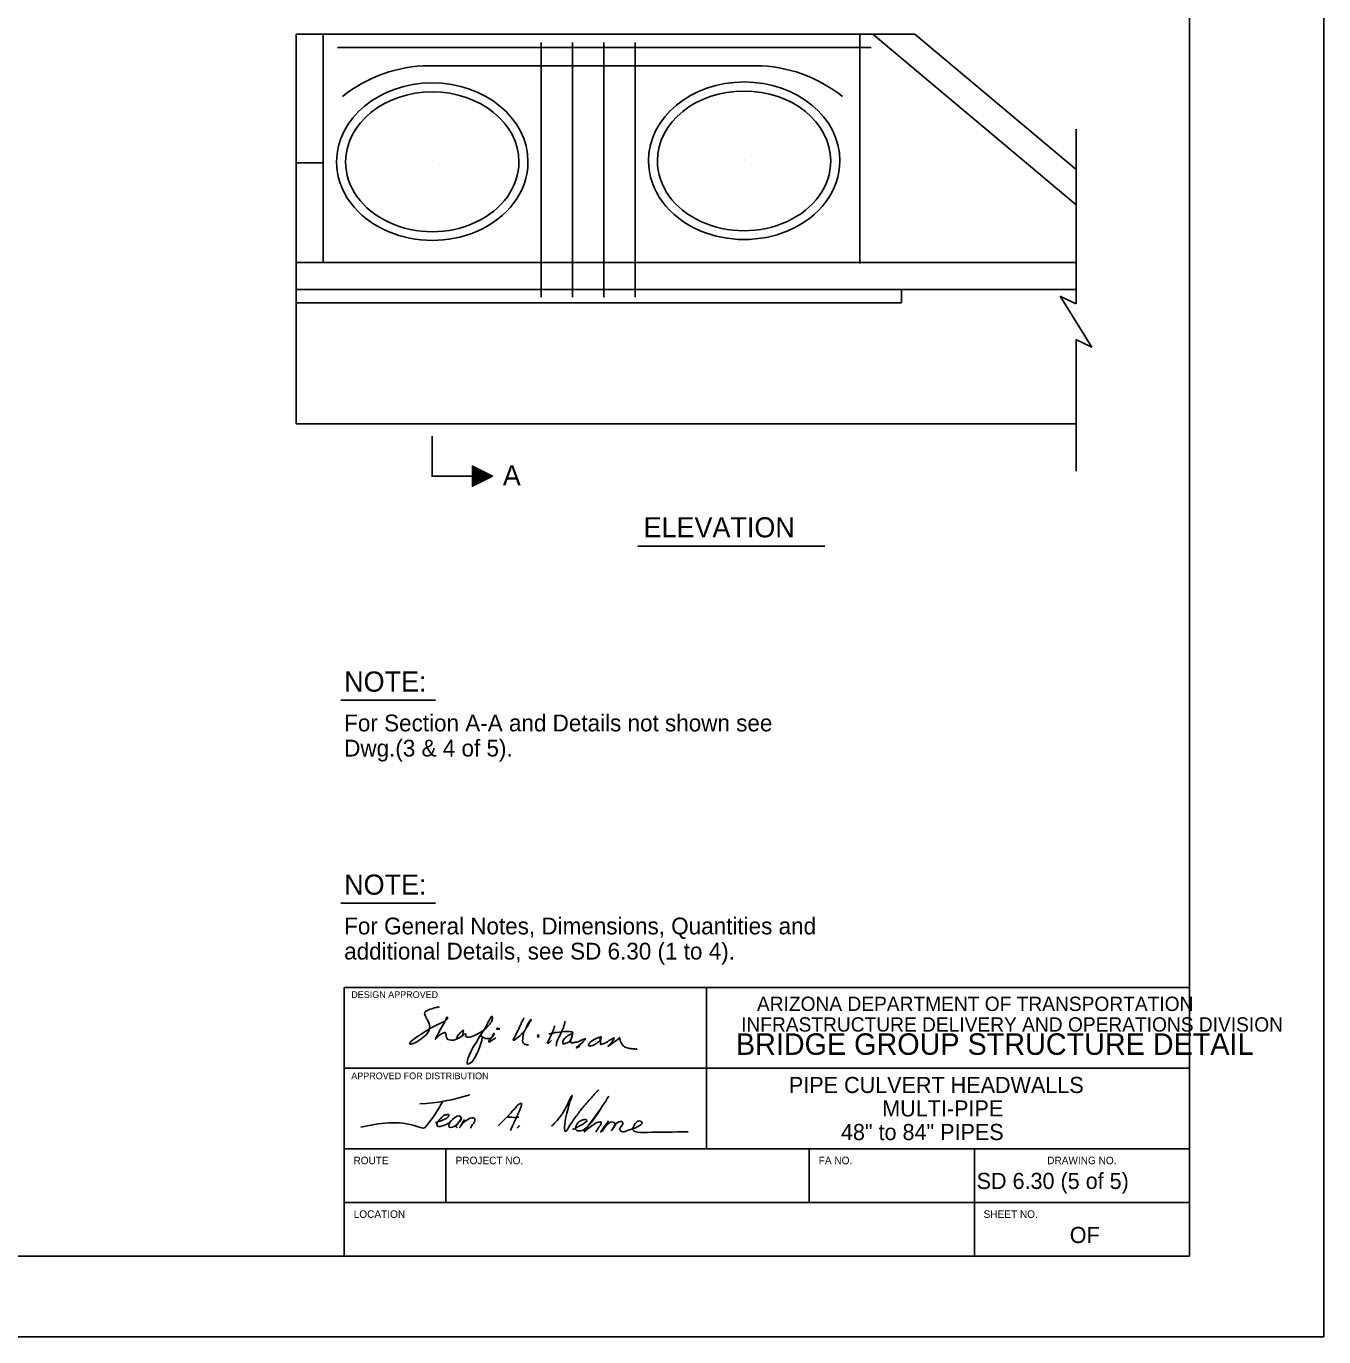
# Model space of a CAD drawing. Extents: x -0.08 to 2.83, y -0.03 to 1.92.
# Drawn here: x 1.827 to 2.833, y 0 to 1.016 of the extents above; entities that cross this region are included whole.
import ezdxf

# ---------------------------------------------------------------- set-up
doc = ezdxf.new("R2010")
doc.units = 0
for name, color, linetype in [('50', 7, 'Continuous'), ('51', 7, 'Continuous'), ('52', 7, 'Continuous'), ('55', 7, 'Continuous'), ('57', 7, 'Continuous'), ('62', 7, 'Continuous'), ('63', 7, 'Continuous')]:
    doc.layers.add(name, color=color, linetype=linetype)

msp = doc.modelspace()

# ---------------------------------------------------------------- linework, layer by layer
at = {"layer": '50'}
for p, q in [((2.0367, 1.0099), (2.5163, 1.0099)), ((2.0367, 0.8951), (2.0367, 1.0099)), ((2.0576, 0.8328), (2.0576, 1.0099)), ((2.4737, 0.8321), (2.4737, 1.0099)), ((2.4838, 1.0099), (2.6414, 0.8777)), ((2.5163, 1.0099), (2.6413, 0.905)), ((2.0367, 0.7078), (2.0367, 0.9944)), ((2.6414, 0.9363), (2.6414, 0.8008)), ((2.0576, 0.9102), (2.0367, 0.9102)), ((2.0749, 0.911), (2.0749, 0.911)), ((2.1424, 0.9117), (2.1424, 0.9117)), ((2.3167, 0.9117), (2.3167, 0.9117)), ((2.384, 0.9117), (2.384, 0.9117)), ((2.3842, 0.9124), (2.3842, 0.9124)), ((2.0367, 0.8328), (2.6414, 0.8328)), ((2.0367, 0.812), (2.6414, 0.812)), ((2.5059, 0.8016), (2.5059, 0.812)), ((2.6289, 0.8069), (2.6412, 0.8008)), ((2.6289, 0.8069), (2.6535, 0.7672)), ((2.0367, 0.8016), (2.5059, 0.8016)), ((2.6412, 0.787), (2.6412, 0.787)), ((2.6412, 0.7733), (2.6535, 0.7672)), ((2.6414, 0.7733), (2.6414, 0.6712)), ((2.0367, 0.7078), (2.6414, 0.7078))]:
    msp.add_line(p, q, dxfattribs=at)
at = {"layer": '51'}
for p, q in [((2.0687, 0.9995), (2.4825, 0.9995)), ((2.2266, 0.806), (2.2266, 1.0036)), ((2.2509, 0.806), (2.2509, 1.0036)), ((2.2752, 0.806), (2.2752, 1.0036)), ((2.2995, 0.806), (2.2995, 1.0036)), ((2.1396, 0.9855), (2.393, 0.9855))]:
    msp.add_line(p, q, dxfattribs=at)
for centre, start, end in [((2.1406, 0.8765), 90.5076, 128.604), ((2.3921, 0.8765), 51.396, 89.4924)]:
    msp.add_arc(centre, 0.109, start, end, dxfattribs=at)
at = {"layer": '52'}
for centre, major_axis, ratio, start_param, end_param in [((2.1422, 0.911), (-0.0742, 0), 0.824448, 3.141593, 6.283185), ((2.384, 0.9117), (-0.0742, 0), 0.824448, 3.141593, 6.283185), ((2.3839, 0.9117), (-0.0672, 0), 0.80633, 3.141593, 6.283185), ((2.1422, 0.911), (-0.0672, 0), 0.80633, 3.141593, 6.283185), ((2.1422, 0.911), (-0.0742, 0), 0.821526, 0, 1.092867), ((2.1422, 0.911), (-0.0672, 0), 0.80633, 0, 3.141593), ((2.1422, 0.911), (-0.0742, 0), 0.821526, 2.043996, 3.141597), ((2.384, 0.9117), (-0.0742, 0), 0.821526, 0, 1.092867), ((2.3839, 0.9117), (-0.0672, 0), 0.80633, 0, 3.141593), ((2.384, 0.9117), (-0.0742, 0), 0.821526, 2.043996, 3.141597), ((2.1422, 0.911), (-0.0742, 0), 0.821526, 1.092853, 2.043994), ((2.384, 0.9117), (-0.0742, 0), 0.821526, 1.092853, 2.043994)]:
    msp.add_ellipse(centre, major_axis=major_axis, ratio=ratio, start_param=start_param, end_param=end_param, dxfattribs=at)
at = {"layer": '55'}
msp.add_lwpolyline([(2.142, 0.6984), (2.142, 0.6672), (2.1733, 0.6672), (2.1733, 0.6594), (2.1889, 0.6673), (2.1733, 0.6751), (2.1733, 0.6673), (2.1744, 0.6672), (2.1744, 0.661), (2.1869, 0.6673), (2.1744, 0.6735), (2.1744, 0.6673), (2.1754, 0.6672), (2.1754, 0.6623), (2.1854, 0.6673), (2.1754, 0.6723), (2.1754, 0.6673), (2.1763, 0.6672), (2.1763, 0.6637), (2.1833, 0.6672), (2.1763, 0.6708), (2.1763, 0.6673), (2.1773, 0.6672), (2.1773, 0.6647), (2.1822, 0.6672), (2.1773, 0.6697), (2.1773, 0.6673), (2.1778, 0.6672), (2.1778, 0.6658), (2.1807, 0.6672), (2.1778, 0.6687), (2.1778, 0.6673), (2.1784, 0.6672), (2.1784, 0.6666), (2.1795, 0.6672), (2.1784, 0.6677), (2.1784, 0.6673)], dxfattribs=at)
at = {"layer": '57'}
for p, q in [((2.3015, 0.613), (2.4465, 0.613)), ((2.0713, 0.4935), (2.1448, 0.4935)), ((2.0713, 0.3361), (2.1448, 0.3361))]:
    msp.add_line(p, q, dxfattribs=at)
for points in [[(2.1477, 0.2556), (2.1468, 0.2557), (2.1458, 0.2554), (2.1449, 0.2553), (2.144, 0.255), (2.1431, 0.2548), (2.142, 0.2543), (2.1404, 0.2539), (2.139, 0.2533), (2.1381, 0.2528), (2.1376, 0.2526), (2.1371, 0.2524), (2.1366, 0.2519), (2.1364, 0.2514), (2.1363, 0.2504), (2.1365, 0.2499), (2.1367, 0.2491), (2.1371, 0.2482), (2.1375, 0.2473), (2.138, 0.2463), (2.1385, 0.2457), (2.1391, 0.2444), (2.1395, 0.2436), (2.1399, 0.2429), (2.1401, 0.2414), (2.1402, 0.2405), (2.1401, 0.2395), (2.1397, 0.238), (2.1389, 0.2363), (2.1382, 0.2352), (2.1366, 0.2333), (2.1351, 0.2323), (2.1333, 0.2307), (2.1317, 0.2297), (2.1303, 0.2288), (2.1288, 0.228), (2.1273, 0.2273), (2.1258, 0.2268), (2.125, 0.2269), (2.1246, 0.2276), (2.1248, 0.228), (2.1254, 0.2285), (2.1258, 0.2291), (2.1269, 0.23), (2.129, 0.2315), (2.1299, 0.2322), (2.1315, 0.2334), (2.1333, 0.2345), (2.1352, 0.2357), (2.1368, 0.2366), (2.1413, 0.2395), (2.1456, 0.2416), (2.1476, 0.2427), (2.1498, 0.2437), (2.1514, 0.2445), (2.1527, 0.2452), (2.1536, 0.2459), (2.154, 0.2465), (2.154, 0.2477), (2.1536, 0.2479), (2.1534, 0.2477), (2.1533, 0.2474), (2.1519, 0.2441), (2.151, 0.2423), (2.1479, 0.2371), (2.1462, 0.2339), (2.1454, 0.2326), (2.1446, 0.2309), (2.1447, 0.2307), (2.1462, 0.2324), (2.1479, 0.2338), (2.1493, 0.2349), (2.1504, 0.2355), (2.1503, 0.2355), (2.1517, 0.236), (2.1523, 0.2358), (2.1525, 0.2355), (2.1529, 0.2341), (2.153, 0.2328), (2.1535, 0.2316), (2.1542, 0.2306), (2.1566, 0.2301), (2.159, 0.2301), (2.1606, 0.2308), (2.1633, 0.2318), (2.1649, 0.233), (2.1659, 0.2341), (2.1662, 0.2362), (2.1665, 0.2374), (2.1662, 0.2377), (2.1657, 0.2374), (2.1644, 0.2361), (2.163, 0.2346), (2.1624, 0.234), (2.1617, 0.2332), (2.1613, 0.2319), (2.1615, 0.2311), (2.1631, 0.2319), (2.165, 0.2331), (2.1666, 0.2342), (2.1675, 0.2349)], [(2.1675, 0.2349), (2.1677, 0.235), (2.168, 0.235), (2.1683, 0.2343), (2.1681, 0.2332), (2.1685, 0.2325), (2.1694, 0.2323), (2.1707, 0.2323), (2.1722, 0.2326), (2.1743, 0.2334), (2.1771, 0.2347), (2.1792, 0.2359), (2.1811, 0.237), (2.184, 0.2394), (2.1867, 0.2425), (2.1874, 0.2434), (2.188, 0.2441), (2.1888, 0.2468), (2.1886, 0.2482), (2.188, 0.2484), (2.1852, 0.2437), (2.1836, 0.2401), (2.1786, 0.2322), (2.1764, 0.2285), (2.1737, 0.2244), (2.1708, 0.2182), (2.1698, 0.2158), (2.1692, 0.2126), (2.1693, 0.2119), (2.1701, 0.2114), (2.1719, 0.2123), (2.173, 0.2133), (2.1749, 0.2161), (2.1775, 0.2209), (2.1789, 0.2242), (2.1797, 0.2265), (2.1806, 0.2298), (2.1808, 0.2318), (2.1807, 0.2332), (2.1801, 0.2336), (2.1797, 0.2338), (2.18, 0.2331), (2.1807, 0.2327), (2.1813, 0.2322), (2.1824, 0.2317), (2.1835, 0.2313), (2.1841, 0.2313), (2.1858, 0.2312), (2.1865, 0.2313), (2.1879, 0.2317), (2.1891, 0.2327), (2.1894, 0.233), (2.1901, 0.2346), (2.1902, 0.2351), (2.1898, 0.2354), (2.1884, 0.2324), (2.1867, 0.2305), (2.1863, 0.2297), (2.186, 0.229), (2.1862, 0.2285), (2.1886, 0.23), (2.1895, 0.2305), (2.1906, 0.2312), (2.1914, 0.2318)], [(2.2132, 0.2473), (2.2128, 0.2463), (2.2119, 0.2446), (2.2111, 0.2429), (2.2099, 0.24), (2.2092, 0.2388), (2.2084, 0.2371), (2.2075, 0.2353), (2.2066, 0.2336), (2.2059, 0.2321), (2.2052, 0.2309), (2.205, 0.2303), (2.205, 0.23), (2.2051, 0.2299), (2.2054, 0.2298), (2.2057, 0.23), (2.2065, 0.2305), (2.2074, 0.2312), (2.2088, 0.2323), (2.2101, 0.2334), (2.2113, 0.2347), (2.2122, 0.2357), (2.2133, 0.2367), (2.214, 0.2375), (2.2148, 0.239), (2.216, 0.2409), (2.2167, 0.242), (2.2178, 0.2441), (2.2184, 0.2448), (2.2189, 0.2456), (2.2189, 0.2458), (2.2188, 0.2459), (2.2187, 0.246), (2.2185, 0.2459), (2.2181, 0.2452), (2.2172, 0.2441), (2.216, 0.242), (2.2157, 0.2413), (2.2153, 0.2404), (2.2149, 0.2396), (2.2139, 0.2375), (2.2133, 0.236), (2.213, 0.2348), (2.2127, 0.2337), (2.2125, 0.2324), (2.2123, 0.2307), (2.2122, 0.2295), (2.2123, 0.2283), (2.2126, 0.2278), (2.2132, 0.2273), (2.2138, 0.2269), (2.2143, 0.2267), (2.215, 0.2265), (2.2156, 0.2264), (2.2162, 0.2264), (2.2167, 0.2264)], [(2.2447, 0.2448), (2.245, 0.2443), (2.245, 0.2437), (2.2449, 0.2432), (2.2447, 0.2423), (2.2443, 0.2408), (2.2439, 0.2397), (2.2432, 0.238), (2.2427, 0.237), (2.2421, 0.2359), (2.241, 0.2334), (2.2406, 0.2326), (2.2395, 0.2304), (2.2393, 0.23), (2.239, 0.2291), (2.2386, 0.2277), (2.2384, 0.2267), (2.2382, 0.2256), (2.2381, 0.2252)], [(2.1947, 0.2388), (2.1943, 0.2388), (2.1938, 0.2389), (2.1934, 0.2391), (2.1931, 0.2393), (2.1928, 0.2393), (2.1925, 0.2393), (2.1924, 0.2392), (2.1922, 0.239), (2.1922, 0.2389), (2.1922, 0.2386), (2.1925, 0.2385), (2.1927, 0.2385), (2.193, 0.2385), (2.1935, 0.2386), (2.1938, 0.2386), (2.1942, 0.2386), (2.1946, 0.2387), (2.1947, 0.2387)], [(2.2244, 0.2324), (2.2247, 0.2331), (2.2246, 0.2338), (2.2244, 0.2341), (2.2241, 0.2341), (2.224, 0.2339), (2.2239, 0.2332), (2.224, 0.2326), (2.2242, 0.2323), (2.2243, 0.2322), (2.2244, 0.2322), (2.2244, 0.2324)], [(2.2371, 0.2412), (2.2367, 0.24), (2.2364, 0.239), (2.2358, 0.2372), (2.235, 0.2353), (2.2346, 0.2345), (2.2341, 0.2333), (2.2333, 0.2317), (2.2327, 0.2306), (2.2322, 0.2297), (2.2317, 0.2288), (2.2315, 0.2282), (2.2315, 0.2278), (2.2316, 0.2276), (2.2318, 0.2276), (2.232, 0.2276), (2.2326, 0.228), (2.2331, 0.2284), (2.2334, 0.2286), (2.2336, 0.2288), (2.2338, 0.2289), (2.234, 0.2291), (2.2342, 0.2293), (2.2344, 0.2295), (2.2345, 0.2296), (2.2347, 0.2298)], [(2.2325, 0.2346), (2.2332, 0.2348), (2.2342, 0.235), (2.2357, 0.2354), (2.2374, 0.2358), (2.2388, 0.2359), (2.2409, 0.2362), (2.243, 0.2364), (2.2448, 0.2366), (2.2463, 0.2366), (2.2475, 0.2366), (2.2482, 0.2366), (2.2495, 0.2365), (2.2505, 0.2364), (2.2509, 0.2362), (2.2511, 0.2357), (2.2507, 0.2337), (2.2506, 0.2334), (2.2501, 0.2318), (2.2497, 0.2308), (2.2492, 0.2298), (2.249, 0.2294), (2.2488, 0.2291), (2.2486, 0.2288), (2.2479, 0.2285), (2.2467, 0.2278), (2.2457, 0.2276), (2.2449, 0.2273), (2.2445, 0.2272), (2.244, 0.2272), (2.2435, 0.2274), (2.2433, 0.2275), (2.2433, 0.2277), (2.2433, 0.2281), (2.2433, 0.2288), (2.2435, 0.2293), (2.2437, 0.2298), (2.2441, 0.2306), (2.2447, 0.2312), (2.2456, 0.2321), (2.2463, 0.2326), (2.2468, 0.233), (2.2474, 0.2335), (2.2481, 0.2339), (2.249, 0.2344), (2.2496, 0.2347), (2.2503, 0.235), (2.2505, 0.235), (2.2508, 0.2349), (2.2508, 0.2347), (2.2506, 0.2334), (2.2505, 0.2332), (2.2503, 0.2322), (2.2499, 0.231), (2.2495, 0.23), (2.2494, 0.2295), (2.2494, 0.2293), (2.2493, 0.2291), (2.2493, 0.2287), (2.2494, 0.2284), (2.2498, 0.2281), (2.2499, 0.228), (2.2501, 0.228), (2.2505, 0.228), (2.2511, 0.228), (2.2515, 0.228), (2.2519, 0.2281), (2.2525, 0.2282), (2.2531, 0.2283), (2.2537, 0.2284), (2.2544, 0.2285), (2.2551, 0.2288), (2.2563, 0.2293), (2.2578, 0.2299), (2.2589, 0.2304), (2.2597, 0.2307), (2.2602, 0.231), (2.2608, 0.2311), (2.2609, 0.231), (2.2606, 0.2304), (2.26, 0.2298), (2.2593, 0.229), (2.2589, 0.2286), (2.2583, 0.228), (2.2572, 0.227), (2.2541, 0.2242), (2.2538, 0.224), (2.2541, 0.2241), (2.255, 0.2245), (2.2558, 0.2249), (2.2563, 0.2251), (2.2566, 0.2253)], [(2.2723, 0.2303), (2.2721, 0.2318), (2.2715, 0.2323), (2.271, 0.2321), (2.2692, 0.2314), (2.2681, 0.2308), (2.2672, 0.2302), (2.2664, 0.2297), (2.2655, 0.229), (2.2647, 0.2284), (2.2642, 0.2278), (2.2637, 0.2272), (2.2634, 0.2266), (2.2634, 0.2263), (2.2634, 0.2259), (2.2637, 0.2256), (2.264, 0.2255), (2.2644, 0.2254), (2.2646, 0.2254), (2.2652, 0.2255), (2.2655, 0.2256), (2.2664, 0.2258), (2.2678, 0.2263), (2.2686, 0.2269), (2.2695, 0.2275), (2.2703, 0.2281), (2.2711, 0.2287), (2.2718, 0.2294), (2.2724, 0.2301), (2.2731, 0.2315), (2.2732, 0.2322), (2.273, 0.2327), (2.2727, 0.2323), (2.2726, 0.2317), (2.2726, 0.231), (2.2726, 0.2299), (2.2726, 0.2291), (2.2726, 0.2283), (2.2726, 0.2277), (2.2726, 0.2269), (2.2727, 0.2267), (2.2728, 0.2267), (2.2737, 0.227), (2.2747, 0.2272), (2.2754, 0.2275), (2.2761, 0.2279), (2.2764, 0.228), (2.2772, 0.2284), (2.278, 0.2288), (2.2792, 0.2296), (2.2804, 0.2302), (2.2817, 0.2309), (2.2821, 0.2312), (2.283, 0.2318), (2.2831, 0.2317), (2.2829, 0.231), (2.2826, 0.2303), (2.2822, 0.2296), (2.2816, 0.2287), (2.2811, 0.2281), (2.2799, 0.2268), (2.2786, 0.2256), (2.2785, 0.2253), (2.2787, 0.2253), (2.2801, 0.2263), (2.2819, 0.2276), (2.2834, 0.2286), (2.2845, 0.2294), (2.2857, 0.2303), (2.287, 0.2318), (2.2871, 0.2318), (2.2873, 0.2321), (2.2874, 0.232), (2.2877, 0.2307), (2.2879, 0.2299), (2.2882, 0.229), (2.2885, 0.2284), (2.2888, 0.2277), (2.2891, 0.2271), (2.2896, 0.2263), (2.29, 0.2258), (2.2905, 0.2255), (2.2909, 0.2251), (2.2913, 0.2249), (2.2923, 0.2244), (2.2932, 0.2241), (2.2944, 0.2237), (2.2951, 0.2236), (2.2961, 0.2234), (2.297, 0.2233), (2.298, 0.2232), (2.2988, 0.2232), (2.2995, 0.2231), (2.3005, 0.223), (2.3009, 0.2229), (2.3007, 0.2231), (2.3004, 0.2233), (2.3001, 0.2235), (2.2999, 0.2236)]]:
    msp.add_lwpolyline(points, dxfattribs=at)
msp.add_arc((2.1258, 0.3265), 0.1461, 272.671, 288.185, dxfattribs=at)
msp.add_ellipse((2.1597, 0.1667), major_axis=(0.00445, 0.00414), ratio=0.425517, dxfattribs=at)
for points in [[(2.2347, 0.1633), (2.2425, 0.1721), (2.2468, 0.1799), (2.2506, 0.1869), (2.2498, 0.1845), (2.2487, 0.1817), (2.2479, 0.1785), (2.2459, 0.1712), (2.2458, 0.1593), (2.2477, 0.1622), (2.2538, 0.1711), (2.2591, 0.178), (2.2628, 0.1822), (2.2695, 0.1897), (2.2712, 0.1915)], [(2.2791, 0.1865), (2.2669, 0.1687), (2.26, 0.1588), (2.271, 0.1664), (2.2717, 0.1665), (2.2732, 0.1663), (2.2731, 0.1653), (2.2715, 0.1627), (2.269, 0.1586)], [(2.1503, 0.1825), (2.1375, 0.1632), (2.1366, 0.1623), (2.1312, 0.1628), (2.0868, 0.1626)], [(2.1932, 0.1635), (2.199, 0.1693), (2.205, 0.1757), (2.2072, 0.1782), (2.2094, 0.1803), (2.2114, 0.181), (2.2113, 0.1794), (2.2108, 0.1779), (2.2091, 0.1736), (2.205, 0.1646), (2.2028, 0.16)], [(2.251, 0.1608), (2.2596, 0.1653), (2.261, 0.1663), (2.262, 0.1678), (2.2617, 0.1682), (2.26, 0.1684), (2.2567, 0.1671), (2.254, 0.1642), (2.2533, 0.162), (2.2533, 0.161), (2.2558, 0.1596), (2.2601, 0.1609), (2.2641, 0.1646), (2.2731, 0.1773)], [(2.1447, 0.166), (2.1519, 0.1686), (2.154, 0.1699), (2.155, 0.1715), (2.155, 0.1722), (2.1537, 0.1723), (2.1511, 0.1715), (2.1483, 0.1689), (2.1465, 0.1668), (2.1457, 0.1646), (2.1463, 0.1633), (2.1491, 0.1632), (2.153, 0.1646), (2.1551, 0.1658), (2.1571, 0.1674), (2.1572, 0.1674)], [(2.1642, 0.1709), (2.1647, 0.1696), (2.1632, 0.1667), (2.1612, 0.1643), (2.1608, 0.1628), (2.1615, 0.1621)], [(2.1673, 0.1685), (2.1658, 0.1661), (2.1634, 0.1622), (2.1659, 0.1656), (2.1691, 0.168), (2.1705, 0.169), (2.1749, 0.1692), (2.1752, 0.1678), (2.1748, 0.1663), (2.1729, 0.1639), (2.172, 0.1618)], [(2.2002, 0.1702), (2.2027, 0.1703), (2.2053, 0.1701), (2.2092, 0.1703)], [(2.2099, 0.1638), (2.2091, 0.1627), (2.2081, 0.162)], [(2.2788, 0.1674), (2.2734, 0.1591), (2.2738, 0.1595), (2.2796, 0.1659), (2.2814, 0.1666), (2.2834, 0.166), (2.2837, 0.1642), (2.2827, 0.1623), (2.2811, 0.1599), (2.2835, 0.1633), (2.2855, 0.166), (2.2896, 0.1665), (2.2894, 0.164), (2.2876, 0.1603), (2.288, 0.1599), (2.2888, 0.1592), (2.2935, 0.1599), (2.2997, 0.162), (2.3027, 0.1636), (2.3049, 0.1657), (2.3035, 0.1673), (2.3, 0.1659), (2.2983, 0.1632), (2.2979, 0.1623), (2.2978, 0.1605), (2.3016, 0.1586), (2.3087, 0.1584), (2.3405, 0.1588)]]:
    msp.add_spline(points, degree=3, dxfattribs=at)
at = {"layer": '63'}
for p, q in [((2.8333, 1.8333), (2.8333, 0)), ((2.7292, 0.2708), (2.0739, 0.2708)), ((2.0739, 0.2708), (2.0739, 0.0624)), ((2.3549, 0.2708), (2.3549, 0.1458)), ((2.0739, 0.2083), (2.7292, 0.2083)), ((2.0739, 0.2065), (2.0739, 0.2065)), ((2.0739, 0.2065), (2.0739, 0.2065)), ((2.0739, 0.1458), (2.7292, 0.1458)), ((2.0739, 0.144), (2.0739, 0.144)), ((2.0891, 0.1458), (2.0893, 0.1458)), ((2.1527, 0.1041), (2.1527, 0.1458)), ((2.4343, 0.1041), (2.4343, 0.1458)), ((2.0739, 0.1041), (2.5625, 0.1041)), ((2.5625, 0.1041), (2.5625, 0.0624)), ((2.7292, 0.0624), (2.7292, 0.1041)), ((2.0739, 0.0624), (2.7292, 0.0624)), ((2.8333, 0), (0, 0)), ((2.83, 0.0003), (2.83, 0.0003))]:
    msp.add_line(p, q, dxfattribs=at)
msp.add_lwpolyline([(0.1667, 0.0624), (0.1667, 1.7708), (2.7292, 1.7708), (2.7292, 0.1041), (2.5625, 0.1041), (2.5625, 0.1458), (2.0739, 0.1458), (2.0739, 0.0624)], close=True, dxfattribs=at)

# ---------------------------------------------------------------- texts
at = {"layer": '55'}
for s, p in [('DESIGN APPROVED', (2.0794, 0.2627)), ('APPROVED FOR DISTRIBUTION', (2.0794, 0.1997))]:
    msp.add_text(s, height=0.005208, dxfattribs=at).set_placement(p)
at = {"layer": '57'}
for s, height, p in [('A', 0.0156, (2.1969, 0.6601)), ('ELEVATION', 0.01562, (2.306, 0.6198)), ('NOTE:', 0.01562, (2.0739, 0.5002)), ('For Section A-A and Details not shown see', 0.013021, (2.0739, 0.4694)), ('Dwg.(3 & 4 of 5).', 0.013021, (2.0739, 0.4499)), ('NOTE:', 0.01562, (2.0739, 0.3428)), ('For General Notes, Dimensions, Quantities and', 0.013021, (2.0739, 0.312)), ('additional Details, see SD 6.30 (1 to 4).', 0.013021, (2.0739, 0.2925))]:
    msp.add_text(s, height=height, dxfattribs=at).set_placement(p)
at = {"layer": '62'}
for s, p in [('PIPE CULVERT HEADWALLS', (2.4187, 0.189)), ('MULTI-PIPE', (2.491, 0.1708)), ('48" to 84" PIPES', (2.459, 0.1525)), ('SD 6.30 (5 of 5)', (2.5642, 0.1146))]:
    msp.add_text(s, height=0.0125, dxfattribs=at).set_placement(p)
at = {"layer": '63'}
for s, height, p in [('ARIZONA DEPARTMENT OF TRANSPORTATION', 0.011108, (2.3939, 0.2526)), ('INFRASTRUCTURE DELIVERY AND OPERATIONS DIVISION', 0.011108, (2.3816, 0.2366)), ('BRIDGE GROUP STRUCTURE DETAIL', 0.016667, (2.3776, 0.2186)), ('ROUTE', 0.00583, (2.0811, 0.1338)), ('PROJECT NO.', 0.005833, (2.1603, 0.1338)), ('FA NO.', 0.00583, (2.4418, 0.1338)), ('DRAWING NO.', 0.005833, (2.6189, 0.1338)), ('LOCATION', 0.00583, (2.0813, 0.0922)), ('SHEET NO.', 0.00583, (2.5696, 0.0922)), ('OF', 0.0125, (2.6364, 0.0727))]:
    msp.add_text(s, height=height, dxfattribs=at).set_placement(p)

doc.saveas('drawing.dxf')
